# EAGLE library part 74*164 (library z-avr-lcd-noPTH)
8-bit parallel out SHIFT REGISTER
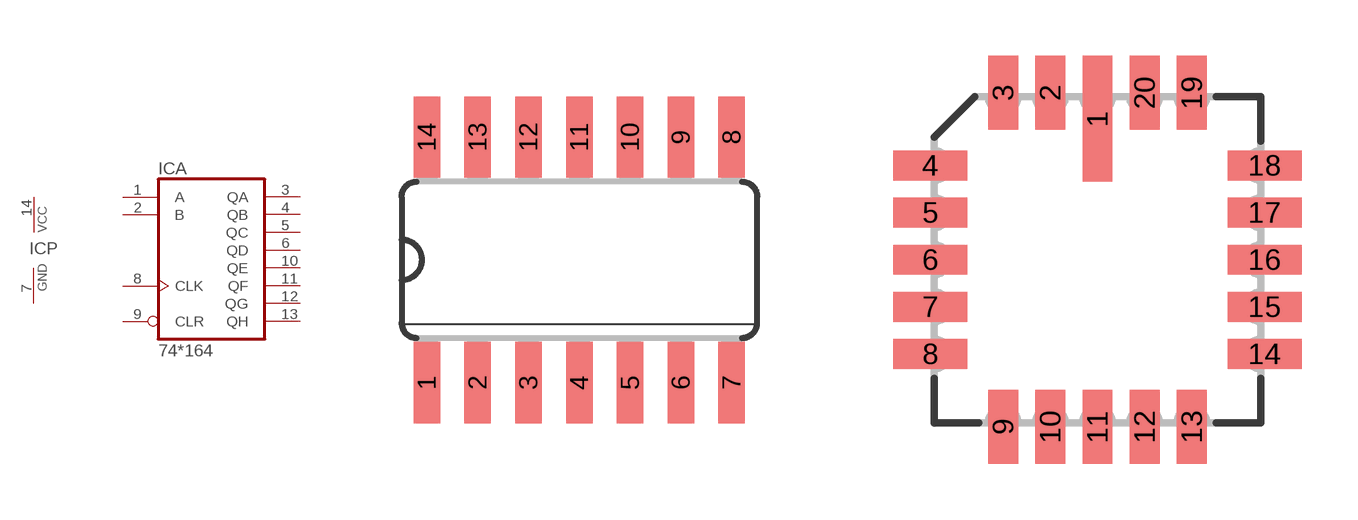
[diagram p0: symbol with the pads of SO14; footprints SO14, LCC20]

Designator prefix IC; gates A=74164 P=PWRN

## 74164D, 74AC164D, 74ACT164D, 74HC164D, 74HCT164D, 74LS164D  [SO14]
1  A:A  in
2  A:B  in
3  A:QA  out
4  A:QB  out
5  A:QC  out
6  A:QD  out
7  P:GND  pwr
8  A:CLK  in
9  A:CLR  in
10  A:QE  out
11  A:QF  out
12  A:QG  out
13  A:QH  out
14  P:VCC  pwr

## 74164FK, 74AC164FK, 74ACT164FK, 74HC164FK, 74HCT164FK, 74LS164FK  [LCC20]
2  A:A  in
3  A:B  in
4  A:QA  out
6  A:QB  out
8  A:QC  out
9  A:QD  out
10  P:GND  pwr
12  A:CLK  in
13  A:CLR  in
14  A:QE  out
16  A:QF  out
18  A:QG  out
19  A:QH  out
20  P:VCC  pwr

## 74164N, 74AC164N, 74ACT164N, 74HC164N, 74HCT164N, 74LS164N  [DIL14]
Pads as for SO14

## Footprint SO14 (pad centres in mm)
Small Outline package 150 mil
smd 0.66 x 2.032: 1 -3.81,-3.073; 2 -2.54,-3.073; 3 -1.27,-3.073; 4 0,-3.073; 5 1.27,-3.073; 6 2.54,-3.073; 7 3.81,-3.073; 8 3.81,3.073; 9 2.54,3.073; 10 1.27,3.073; 11 0,3.073; 12 -1.27,3.073; 13 -2.54,3.073; 14 -3.81,3.073

## Footprint LCC20 (pad centres in mm)
Leadless Chip Carrier Ceramic Package
smd 0.8 x 3.4: 1 0,3.8
smd 0.8 x 2: 2 -1.27,4.5; 3 -2.54,4.5; 9 -2.54,-4.5; 10 -1.27,-4.5; 11 0,-4.5; 12 1.27,-4.5; 13 2.54,-4.5; 19 2.54,4.5; 20 1.27,4.5
smd 2 x 0.8: 4 -4.5,2.54; 5 -4.5,1.27; 6 -4.5,0; 7 -4.5,-1.27; 8 -4.5,-2.54; 14 4.5,-2.54; 15 4.5,-1.27; 16 4.5,0; 17 4.5,1.27; 18 4.5,2.54

## Footprint DIL14 (pad centres in mm)
Dual In Line Package
drill 0.813 long: 1 -7.62,-3.81; 2 -5.08,-3.81; 3 -2.54,-3.81; 4 0,-3.81; 5 2.54,-3.81; 6 5.08,-3.81; 7 7.62,-3.81; 8 7.62,3.81; 9 5.08,3.81; 10 2.54,3.81; 11 0,3.81; 12 -2.54,3.81; 13 -5.08,3.81; 14 -7.62,3.81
